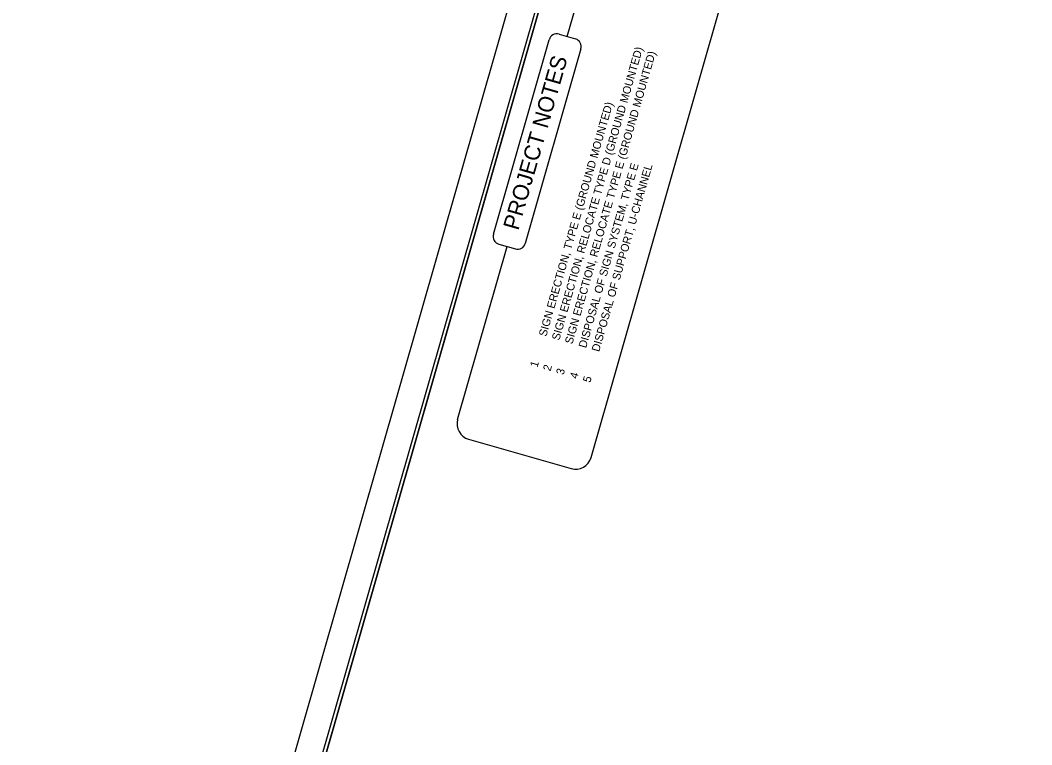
# Model space of a CAD drawing. Extents: x 2096093 to 2098911, y 683546 to 689764.
# Drawn here: x 2096990 to 2097748, y 688738 to 689281 of the extents above; entities that cross this region are included whole.
import ezdxf

# ---------------------------------------------------------------- set-up
doc = ezdxf.new("R2010")
doc.units = 0
for name, color, linetype in [('Default', 7, 'Continuous'), ('Scratch_Level_5', 7, 'Continuous'), ('Sheet Plan CELL', 7, 'Continuous'), ('Sheet Plot Border Inside CELL', 7, 'Continuous'), ('Sheet Plot Border Outside CELL', 7, 'Continuous'), ('Sheet Title CELL', 7, 'Continuous')]:
    doc.layers.add(name, color=color, linetype=linetype)

msp = doc.modelspace()

# ---------------------------------------------------------------- linework, layer by layer
at = {"layer": 'Scratch_Level_5'}
msp.add_lwpolyline([(2098117.81, 688054.49), (2097347.73, 688084.03), (2097057.83, 688167.01), (2097419.22, 689429.54), (2097641.13, 689365.99), (2097692.54, 689545.54), (2098409.79, 689340.16), (2098316.63, 689014.71), (2098387.02, 688994.56)], close=True, dxfattribs=at)
at = {"layer": 'Sheet Plan CELL'}
msp.add_lwpolyline([(2097470.8, 689609.08), (2097057.86, 688167.12), (2098067.29, 687878.05), (2098480.22, 689319.99)], close=True, dxfattribs=at)
at = {"layer": 'Sheet Plot Border Inside CELL'}
msp.add_lwpolyline([(2098027.26, 687729.7), (2098485.9, 689331.31), (2097471.68, 689621.77), (2097013.02, 688020.15)], close=True, dxfattribs=at)
msp.add_lwpolyline([(2098027.26, 687729.7), (2098485.9, 689331.31), (2097471.68, 689621.77), (2097013.02, 688020.15)], close=True, dxfattribs=at)
at = {"layer": 'Sheet Plot Border Outside CELL'}
msp.add_lwpolyline([(2098042.9, 687711.7), (2098506.38, 689330.14), (2097453.69, 689631.6), (2096990.22, 688013.15)], close=True, dxfattribs=at)
msp.add_lwpolyline([(2098042.9, 687711.7), (2098506.38, 689330.14), (2097453.69, 689631.6), (2096990.22, 688013.15)], close=True, dxfattribs=at)
at = {"layer": 'Sheet Title CELL'}
for p, q in [((2097400.17, 689268.49), (2097437.27, 689398.08)), ((2097418.03, 688952.89), (2097537.27, 689369.45)), ((2097393.99, 689270.26), (2097406.35, 689266.72)), ((2097344.82, 689120.29), (2097386.57, 689266.14)), ((2097410.47, 689259.3), (2097368.72, 689113.45)), ((2097318.02, 688981.52), (2097355.12, 689111.1)), ((2097348.94, 689112.87), (2097361.3, 689109.34)), ((2097326.26, 688966.68), (2097403.19, 688944.66))]:
    msp.add_line(p, q, dxfattribs=at)
for centre, radius, start, end in [((2097392.34, 689264.49), 6, 74.02589, 164.02589), ((2097404.7, 689260.95), 6, 344.02589, 74.02589), ((2097350.59, 689118.64), 6, 164.02589, 254.02589), ((2097362.95, 689115.1), 6, 254.02589, 344.02589), ((2097329.56, 688978.22), 12, 164.02589, 254.02589), ((2097406.49, 688956.2), 12, 254.02589, 344.02589)]:
    msp.add_arc(centre, radius, start, end, dxfattribs=at)

# ---------------------------------------------------------------- texts
at = {"layer": 'Default'}
for s, height, p in [('SIGN ERECTION, RELOCATE TYPE D (GROUND MOUNTED)', 6, (2097394.2, 689040.39)), ('SIGN ERECTION, RELOCATE TYPE E (GROUND MOUNTED)', 6, (2097403.97, 689037.59)), ('PROJECT NOTES', 12, (2097363.45, 689122.7)), ('SIGN ERECTION, TYPE E (GROUND MOUNTED)', 6, (2097384.42, 689043.18)), ('DISPOSAL OF SIGN SYSTEM, TYPE E', 6, (2097414.27, 689034.64)), ('DISPOSAL OF SUPPORT, U-CHANNEL', 6, (2097424.05, 689031.84)), ('1', 6, (2097377.82, 689020.11)), ('2', 6, (2097387.59, 689017.31)), ('3', 6, (2097397.37, 689014.51)), ('4', 6, (2097407.67, 689011.56)), ('5', 6, (2097417.44, 689008.77))]:
    msp.add_text(s, height=height, rotation=74.02589, dxfattribs=at).set_placement(p)

doc.saveas('drawing.dxf')
